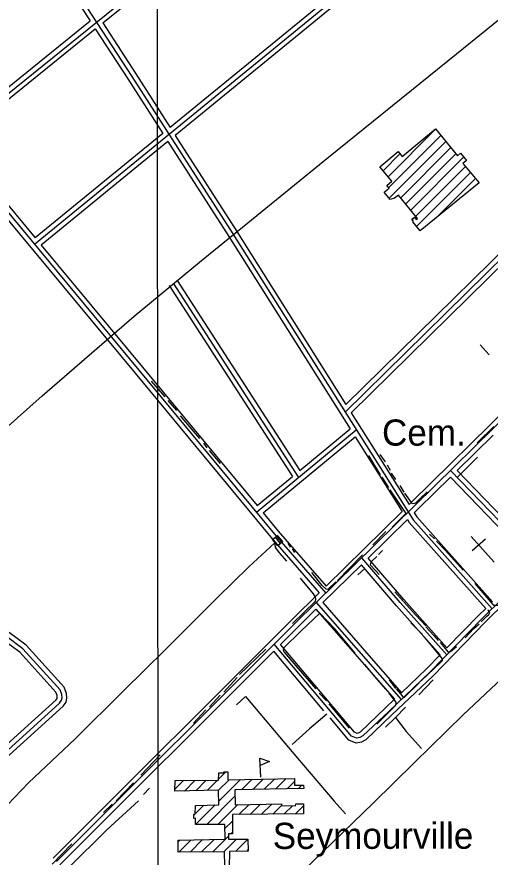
# Model space of a CAD drawing. Extents: x 3297772 to 3335630, y 634068 to 659439.
# Drawn here: x 3311952 to 3313452, y 644520 to 647184 of the extents above; entities that cross this region are included whole.
import ezdxf

# ---------------------------------------------------------------- set-up
doc = ezdxf.new("R2010")
doc.units = 0
for name, color, linetype in [('V-BLDG-IDEN', 7, 'Continuous'), ('V-BLDG-OTLN', 7, 'Continuous'), ('V-BRDG-OTLN', 7, 'Continuous'), ('V-GRID-MAJR', 7, 'Continuous'), ('V-ROAD-CNTR', 7, 'Continuous'), ('V-SITE-OTLN', 7, 'Continuous'), ('V-SITE-OTLN-IDEN', 7, 'Continuous'), ('V-TOPO-SHOR', 7, 'Continuous')]:
    doc.layers.add(name, color=color, linetype=linetype)

msp = doc.modelspace()

# ---------------------------------------------------------------- linework, layer by layer
at = {"layer": 'V-BLDG-OTLN'}
for p, q in [((3313128.5, 646677), (3313278.9, 646827.6)), ((3313130.2, 646643.2), (3313294.9, 646808.2)), ((3313131.6, 646609.2), (3313310.8, 646788.8)), ((3313112.3, 646696.1), (3313165.8, 646749.7)), ((3313168.3, 646610.6), (3313326.8, 646769.4)), ((3313184.1, 646591.1), (3313342.7, 646750.1)), ((3313199.9, 646571.5), (3313368, 646740)), ((3313215.7, 646552), (3313373.4, 646710)), ((3313218.2, 646519.1), (3313389.5, 646690.7)), ((3313281.8, 646547.4), (3313405.5, 646671.4)), ((3313204.6, 646540.8), (3313211.9, 646548.2)), ((3312725.4, 644773.4), (3312722.4, 644833.3)), ((3312591.7, 644767.3), (3312614.6, 644790.2)), ((3312453.3, 644735), (3312480.8, 644762.4)), ((3312483.1, 644729.4), (3312516.6, 644762.9)), ((3312519.2, 644730.1), (3312552.4, 644763.3)), ((3312555.3, 644730.8), (3312588.2, 644763.8)), ((3312591.4, 644731.6), (3312624.7, 644764.9)), ((3312592.2, 644697.1), (3312660.8, 644765.7)), ((3312664, 644733.5), (3312696.9, 644766.4)), ((3312700.1, 644734.2), (3312733, 644767.1)), ((3312736.1, 644734.9), (3312769.1, 644767.9)), ((3312772.2, 644735.6), (3312805.2, 644768.6)), ((3312808.3, 644736.4), (3312831.4, 644759.5)), ((3312844.3, 644737.1), (3312854.7, 644747.4)), ((3312553.8, 644623.4), (3312643.3, 644712.9)), ((3312517.1, 644657.3), (3312544.3, 644684.5)), ((3312518.6, 644623.6), (3312580.6, 644685.5)), ((3312589.3, 644623.5), (3312652.1, 644686.3)), ((3312655.8, 644654.7), (3312688, 644686.8)), ((3312691.7, 644655.1), (3312723.9, 644687.4)), ((3312727.5, 644655.6), (3312759.8, 644687.9)), ((3312763.3, 644656.1), (3312790.5, 644683.2)), ((3312799.2, 644656.6), (3312825.1, 644682.5)), ((3312835, 644657.1), (3312860.1, 644682.1)), ((3312512.9, 644653.2), (3312515.5, 644655.7)), ((3312611.6, 644610.5), (3312635.3, 644634.1)), ((3312573.2, 644536.8), (3312622.9, 644586.4)), ((3312630, 644593.5), (3312635.4, 644599)), ((3312463.2, 644568.2), (3312468.9, 644573.8)), ((3312465.9, 644535.5), (3312504.9, 644574.5)), ((3312501.7, 644536), (3312540.9, 644575.2)), ((3312537.5, 644536.4), (3312577, 644575.8)), ((3312609, 644537.2), (3312648.7, 644576.8)), ((3312645.7, 644538.6), (3312684.2, 644577)), ((3312681.6, 644539.1), (3312685.1, 644542.6))]:
    msp.add_line(p, q, dxfattribs=at)
for points in [[(3313416.9, 646658), (3313230, 646505), (3313206.6, 646533.6), (3313209.1, 646535.6), (3313203.6, 646542.3), (3313211.6, 646548.8), (3313217.5, 646541.6), (3313221.6, 646545), (3313161.8, 646618.2), (3313148.2, 646609.5), (3313135.1, 646604.4), (3313115.9, 646627.8), (3313131.8, 646640.9), (3313124.8, 646649.5), (3313140.4, 646662.5), (3313102.1, 646708.7), (3313159.8, 646756.7), (3313173.1, 646740.8), (3313278.4, 646828.5), (3313348, 646743.6), (3313358.2, 646752), (3313377, 646729), (3313365.5, 646719.5)], [(3312722.4, 644833.3), (3312752.9, 644823.3), (3312723.5, 644810.2)]]:
    msp.add_lwpolyline(points, close=True, dxfattribs=at)
msp.add_lwpolyline([(3312612.4, 644448.2), (3312609.9, 644537), (3312463.6, 644535.3), (3312463.2, 644573.6), (3312611.9, 644576.4), (3312611.5, 644623.4), (3312518.6, 644623.3), (3312518.2, 644643.2), (3312512.9, 644642.1), (3312512.9, 644655), (3312517, 644656.2), (3312518.3, 644683.8), (3312592.4, 644685.8), (3312591.5, 644731.6), (3312453.3, 644728.8), (3312453.5, 644762.3), (3312591.6, 644764), (3312592.3, 644786.9), (3312608.2, 644787.4), (3312608.2, 644790.4), (3312620.5, 644790.3), (3312620.4, 644765), (3312831.5, 644769.3), (3312831.4, 644747.6), (3312860.7, 644747.4), (3312861.3, 644737.4), (3312643.2, 644733.2), (3312643.6, 644686.1), (3312790.5, 644688.4), (3312790.5, 644683.1), (3312835.2, 644682.3), (3312835.8, 644688.8), (3312859.9, 644689.2), (3312860.9, 644657.5), (3312635.2, 644654.4), (3312635.5, 644593.3), (3312623.1, 644593.4), (3312622.5, 644576.3), (3312684.2, 644577.2), (3312685.2, 644539), (3312625.8, 644538.1), (3312625, 644486.4)], dxfattribs=at)
at = {"layer": 'V-BRDG-OTLN'}
msp.add_line((3312787.7, 645514.3), (3312771.4, 645534.1), dxfattribs=at)
msp.add_lwpolyline([(3312778.5, 645539.8), (3312794.7, 645520), (3312787.7, 645514.3), (3312778.9, 645507), (3312762.6, 645526.9), (3312771.4, 645534.1)], close=True, dxfattribs=at)
at = {"layer": 'V-GRID-MAJR'}
msp.add_spline([(3312404.5, 639457.2), (3312401.9, 642484.8), (3312396.6, 648546.2), (3312391.3, 654607.6), (3312388.7, 657641.3)], degree=3, dxfattribs=at)
at = {"layer": 'V-ROAD-CNTR'}
for points in [[(3311916.5, 646572.9), (3310815.6, 645684.8), (3310810.5, 645685.6), (3310806.2, 645687.1), (3310631.1, 645882.6), (3310630.6, 645887.7), (3310631.8, 645897.6), (3311582.2, 646664.2), (3312459.9, 647374.3), (3313109.4, 647905), (3313632.8, 648328.6), (3314289.8, 648868.9), (3314295.6, 648875.4), (3314300.6, 648887.6), (3314300, 648896.1), (3314294.4, 648906.9), (3314031.9, 649256.5), (3314022.2, 649263.5), (3314012, 649269), (3314003.5, 649267.1), (3313990.6, 649261.9), (3312844, 648362.4), (3311728.2, 647492.7), (3310776.4, 646752.8)], [(3310992.3, 649049.5), (3311234.7, 648679.8), (3311615.8, 648074.4), (3312000.2, 647481.8), (3312316.9, 646995.3), (3312636.3, 646495.5)], [(3315572.2, 647973.4), (3315184.1, 647587), (3314651, 647056.2), (3314360.3, 646769.6), (3313859.8, 646270.2), (3313523.1, 645939.8), (3313214.5, 645635.9), (3312835.3, 645263), (3312078.3, 644506.3)], [(3312224.6, 647164.6), (3312469.4, 647362.7), (3312824.3, 647652.6)], [(3313314.2, 647531.9), (3312008.4, 646462.1)], [(3313309.4, 647508.6), (3312454.3, 646808)], [(3312048.7, 647379.9), (3312184.7, 647170.9)], [(3313067.3, 647349), (3312438.1, 646833.5)], [(3309326.4, 643570.3), (3309969, 644140.9), (3310396.4, 644525.1), (3310968, 645034.1), (3311417.2, 645433.8), (3312033, 645982.1), (3312324.2, 646235.2), (3312530.8, 646406.6), (3312939.4, 646738.7), (3313345.1, 647067.1), (3313626.7, 647296.1)], [(3311660.4, 646746.7), (3312184.7, 647170.9)], [(3311758.3, 646787.3), (3312201.1, 647145.6)], [(3312201.1, 647145.6), (3312304.3, 646987.1), (3312414.7, 646814.3)], [(3312224.6, 647164.6), (3312329.5, 647003.4), (3312438.1, 646833.5)], [(3312414.7, 646814.3), (3312010.5, 646483.1)], [(3312454.3, 646808), (3312648.9, 646503.6)], [(3311737, 646789.5), (3312338.8, 646063.6), (3312768.6, 645544), (3312931, 645357.1)], [(3311758.3, 646787.3), (3312010.5, 646483.1)], [(3312431, 646788.9), (3312029.6, 646460)], [(3312431, 646788.9), (3312623.6, 646487.4)], [(3313757.1, 646683.5), (3312992.3, 645930.7)], [(3313738.6, 646686.4), (3312995, 645954.4)], [(3313753.3, 646658.7), (3313011.4, 645928.4)], [(3311914.4, 646551.9), (3312327.2, 646054), (3312757.2, 645534.3), (3312910.4, 645357.9)], [(3312623.6, 646487.5), (3313007.9, 645877.8)], [(3312636.3, 646495.5), (3313207.4, 645589.3), (3313458.4, 645307.5)], [(3312648.9, 646503.5), (3312995, 645954.4)], [(3312029.6, 646460), (3312350.3, 646073.1), (3312713.5, 645634.2)], [(3312460, 646348.2), (3312848.6, 645745.9)], [(3313914.3, 646345.8), (3313849.2, 646280.9), (3313512.6, 645950.5), (3313204, 645646.6), (3313194.8, 645637.6)], [(3313956.1, 646366.3), (3314000.7, 646283.3), (3314128.1, 646025.3), (3314141, 645987.9), (3314134.8, 645970.7), (3314112.7, 645955.6), (3313979.3, 645821.3), (3313699.6, 645543.6), (3313556.5, 645403.9), (3313426.4, 645276)], [(3313974.6, 646363.6), (3314014.1, 646290.1), (3314141.9, 646031.1), (3314156.9, 645987.8), (3314147.2, 645961), (3314122.4, 645944.1), (3313989.9, 645810.7), (3313710.1, 645532.9), (3313567, 645393.2), (3313436.9, 645265.3)], [(3312434.8, 646331.9), (3312825.3, 645726.7)], [(3312447.4, 646340.1), (3312845.1, 645723.6)], [(3313011.4, 645928.4), (3313194.8, 645637.6)], [(3312711.5, 645613), (3313027.6, 645874.7)], [(3312848.6, 645745.9), (3313007.9, 645877.8)], [(3312732.6, 645611.1), (3313024, 645852.2)], [(3313024, 645852.2), (3313172.9, 645616)], [(3313461.3, 645857.9), (3313347.1, 645745.5)], [(3313326, 645745.8), (3313607.6, 645453.8)], [(3313347.1, 645745.5), (3313607.9, 645475.1)], [(3312713.5, 645634.2), (3312825.3, 645726.7)], [(3313325.8, 645724.4), (3313225, 645625.2), (3313211.1, 645611.6)], [(3313325.8, 645724.4), (3313586.5, 645454.1)], [(3312732.6, 645611.1), (3312780.1, 645553.7), (3312931.8, 645378.9)], [(3313172.9, 645616), (3312931.8, 645378.9)], [(3313211.1, 645611.6), (3313219.5, 645598.4), (3313459.1, 645329.2)], [(3313189.3, 645590.1), (3313065.3, 645468.1)], [(3313189.3, 645590.1), (3313195.4, 645580.3), (3313437.7, 645308.2)], [(3313314, 645160.9), (3313166.8, 645326.8), (3313044.7, 645469)], [(3313314.5, 645182.9), (3313178.1, 645336.7), (3313065.3, 645468.1)], [(3313043.8, 645447), (3312921.4, 645326.7)], [(3313293.5, 645161.3), (3313155.5, 645316.9), (3313043.8, 645447)], [(3311747.1, 644679), (3312099.4, 644998.3), (3312108.7, 645011.6), (3312110.7, 645024.4), (3312110.3, 645038.1), (3312102.1, 645058.6), (3311981.9, 645191.9), (3311929.4, 645230.7), (3311804.2, 645366.1), (3311789.9, 645380.2), (3311776.4, 645389.5), (3311752.8, 645392.5), (3311733.6, 645387.5), (3311717.6, 645378.4), (3311650.4, 645320.8)], [(3311737, 644690.1), (3312088, 645008.3), (3312094.4, 645017.3), (3312095.7, 645025.3), (3312095.4, 645035), (3312089.2, 645050.5), (3311971.7, 645180.7), (3311919.4, 645219.4), (3311793.4, 645355.7), (3311780.3, 645368.5), (3311770.9, 645375.1), (3311753.8, 645377.3), (3311739.3, 645373.5), (3311726.3, 645366), (3311373.5, 645064.1)], [(3311909.3, 644866.5), (3312076.7, 645018.3), (3312080.1, 645023.1), (3312080.6, 645026.2), (3312080.5, 645031.9), (3312076.2, 645042.4), (3311961.6, 645169.6), (3311909.3, 645208.2), (3311782.6, 645345.2), (3311770.7, 645356.9), (3311765.3, 645360.6), (3311754.8, 645362), (3311745, 645359.4), (3311735, 645353.7), (3311383.2, 645052.7)], [(3312910.4, 645357.9), (3312824.7, 645273.6), (3312067.7, 644516.9)], [(3312900, 645305.6), (3312845.9, 645252.3), (3312787.7, 645194.2)], [(3312900, 645305.6), (3313023.2, 645164.1), (3313148.9, 645020.3)], [(3312900.9, 645327.4), (3313034.5, 645173.9), (3313169.6, 645019.4)], [(3312921.4, 645326.7), (3313045.8, 645183.8), (3313170.6, 645041.1)], [(3313437.7, 645308.2), (3313415.9, 645286.7)], [(3313415.7, 645286.5), (3313314.5, 645182.9)], [(3313426.4, 645276), (3313260.2, 645105.8), (3313130.2, 644981.8), (3313048.8, 644904.2), (3313039.2, 644898.9), (3313028.6, 644896.5), (3313012.8, 644903.2), (3312767.4, 645195.1)], [(3313437.1, 645265.6), (3313270.8, 645095.1), (3313140.6, 644971), (3313057.7, 644892), (3313044.6, 644884.7), (3313027.2, 644880.9), (3313003.6, 644890.7), (3312944.4, 644961.3)], [(3312766.4, 645172.9), (3312088.9, 644495.7)], [(3312925.2, 644984.1), (3312766.4, 645172.9)], [(3313148.9, 645020.3), (3313119.9, 644992.7), (3313039.8, 644916.4), (3313033.8, 644913.1), (3313030, 644912.2), (3313021.9, 644915.6), (3312787.7, 645194.2)], [(3313293.5, 645161.3), (3313249.7, 645116.5), (3313170.6, 645041.1)], [(3312934.5, 644973), (3312879.8, 644926.2), (3312824.5, 644876.5)]]:
    msp.add_lwpolyline(points, dxfattribs=at)
at = {"layer": 'V-SITE-OTLN'}
for p, q in [((3313464.3, 645455.5), (3313391.3, 645536.2)), ((3313436.5, 645528.2), (3313394.7, 645490.4))]:
    msp.add_line(p, q, dxfattribs=at)
at = {"layer": 'V-TOPO-SHOR'}
for p, q in [((3313420, 646144.6), (3313448.9, 646112)), ((3312378.3, 646029.1), (3312421.2, 645978.7)), ((3312430.8, 645968.1), (3312457.9, 645935.4)), ((3313410, 645832.9), (3313463.2, 645885.6)), ((3312543.7, 645831.9), (3312554.2, 645817.8)), ((3312562.1, 645809), (3312596.3, 645768.3)), ((3313066.8, 645793.2), (3313103.4, 645732.2)), ((3313102.2, 645795.9), (3313119.2, 645772.7)), ((3313411.5, 645787.6), (3313347.1, 645723.8)), ((3313125.1, 645763.3), (3313134.5, 645746.2)), ((3313137.8, 645737.6), (3313152.3, 645717)), ((3313108.9, 645724.1), (3313129.6, 645691.2)), ((3313165.8, 645698.2), (3313177.7, 645676.7)), ((3313120.9, 645551.8), (3313079.9, 645510.3)), ((3313259.9, 645543.9), (3313275.3, 645529.3)), ((3312819.5, 645502.8), (3312812.3, 645515.6)), ((3312833, 645485.9), (3312825.8, 645497.1)), ((3313098.2, 645478.9), (3313111, 645491.7)), ((3313032.9, 645415.1), (3313054.4, 645434.7)), ((3313149.7, 645360.8), (3313176.1, 645331.6)), ((3313236.2, 645226.2), (3313200.5, 645263.1)), ((3312657.3, 645098.9), (3312741, 645179.4)), ((3312608.2, 645043.1), (3312650.8, 645089.3)), ((3313132.2, 645081.5), (3313151.7, 645054.9)), ((3313271.4, 645081.7), (3313225.9, 645034)), ((3312910.2, 645039.2), (3312933.3, 645015.1)), ((3312563.1, 644996), (3312596.1, 645033.5)), ((3312511.5, 644945), (3312551, 644986.4)), ((3312940.5, 645006.2), (3313005, 644928.2)), ((3313120.3, 644932), (3313152.1, 644962.6)), ((3312345.7, 644779.9), (3312406.9, 644844.5)), ((3312266.8, 644698.6), (3312322.4, 644755.2)), ((3312372.8, 644738.1), (3312353.4, 644718.2)), ((3312226.6, 644661.1), (3312254.7, 644687.4)), ((3312064, 644497.6), (3312126.8, 644562.2))]:
    msp.add_line(p, q, dxfattribs=at)
for points in [[(3312470.2, 645918.6), (3312510.5, 645870), (3312531.5, 645847)], [(3313133.6, 645683.9), (3313184.5, 645609.2), (3313141, 645566.1)], [(3313180.3, 645674.2), (3313201.6, 645644.5), (3313203.3, 645641.9), (3313206.9, 645641), (3313212.1, 645641.8), (3313216.5, 645643.6), (3313229.8, 645656.7), (3313252, 645678.1)], [(3313281.2, 645521.6), (3313310.1, 645491.6), (3313366.2, 645429.8)], [(3312769.8, 645516.6), (3312687.6, 645439.8), (3312588, 645342.9), (3312423.2, 645177.9), (3312290.2, 645047), (3312137.4, 644894.8), (3311989.8, 644755.4), (3311900.5, 644662.7), (3311797.5, 644562.4), (3311663.7, 644429.8), (3311612.3, 644381.1)], [(3312807.2, 645457.9), (3312785.7, 645483.7), (3312774.6, 645497.4), (3312772.2, 645503), (3312769.8, 645516.6)], [(3313046.9, 645478.4), (3313005, 645434.6), (3312968, 645397.1)], [(3313100.4, 645415.7), (3313074.1, 645444), (3313072.4, 645449.1), (3313075.8, 645456.8), (3313092.2, 645473)], [(3312962.4, 645393.1), (3312939, 645369.2), (3312937.4, 645368.4), (3312932.6, 645369.2), (3312919.8, 645380.5), (3312886.4, 645422.3)], [(3312825.5, 645260), (3312898.8, 645331.7), (3312899.6, 645338.1), (3312898.8, 645343.7), (3312892.5, 645354.2), (3312851, 645404.1)], [(3313403.6, 645386.9), (3313460.5, 645320.8), (3313462.2, 645319.1), (3313466.5, 645319.1), (3313480.2, 645319), (3313515.4, 645353)], [(3313176.9, 645329.9), (3313216, 645287), (3313247.5, 645252.6)], [(3313023.8, 645166.9), (3312959.6, 645243.2), (3312911.8, 645293.3), (3312852.9, 645237.6), (3312797.4, 645182.4), (3312795.6, 645175.5), (3312799, 645169.6), (3312836.4, 645125.8), (3312899.1, 645053.7)], [(3313422.7, 645265.5), (3313441.5, 645284.2), (3313447.6, 645289.3), (3313450.1, 645295.3), (3313446.8, 645302.1), (3313444.2, 645303.8)], [(3313372.9, 645215.3), (3313399.5, 645244.2), (3313416.7, 645259.5)], [(3313248.3, 645250.1), (3313272.9, 645222.6), (3313286.5, 645206.3)], [(3313233.8, 645079.3), (3313293, 645135.4), (3313300.8, 645143), (3313300.8, 645148.2), (3313295.7, 645155), (3313257.5, 645201.3), (3313242.2, 645218.5)], [(3313293.3, 645200.3), (3313314.6, 645174.6), (3313318, 645171.1), (3313320.5, 645170.3), (3313325.7, 645172), (3313345.4, 645187.3)], [(3313563.4, 645163.4), (3313488.7, 645086), (3313366.6, 644971.2), (3313211.1, 644818.9), (3313081.1, 644691), (3312887.9, 644503.9), (3312735.3, 644353)], [(3313121, 645052.6), (3313086.5, 645092.3), (3313054.9, 645130.7)], [(3313154.2, 645053.2), (3313172.9, 645030.9), (3313178.9, 645025.7), (3313180.6, 645026.6), (3313227, 645072.5)], [(3313092.4, 644941.4), (3313151.7, 645000.2), (3313154.3, 645005.4), (3313153.5, 645010.6), (3313143.9, 645022.9), (3313132.1, 645039.8)], [(3312648.1, 645002.5), (3312677.1, 645028.6), (3312830.1, 644847.8), (3312957.9, 644697.7), (3312993.5, 644657.3)], [(3313183, 644994.9), (3313152.1, 644962.6), (3313186.1, 644918), (3313234.5, 644864)], [(3312337.3, 644698.2), (3312237.9, 644605.8), (3312115.8, 644485.7), (3312091.2, 644460.5), (3312090.3, 644457.9), (3312090.3, 644453.5), (3312096.4, 644443.9), (3312129.6, 644408.7), (3312152.1, 644385), (3312283.4, 644252.4), (3312333.2, 644204.9), (3312350.9, 644188.6)]]:
    msp.add_lwpolyline(points, dxfattribs=at)

# ---------------------------------------------------------------- texts
at = {"layer": 'V-BLDG-IDEN'}
msp.add_text('Seymourville', height=83, rotation=0.0734, dxfattribs=at).set_placement((3312763.1, 644545.6))
at = {"layer": 'V-SITE-OTLN-IDEN'}
msp.add_text('Cem.', height=83, dxfattribs=at).set_placement((3313109.1, 645824.4))

doc.saveas('drawing.dxf')
